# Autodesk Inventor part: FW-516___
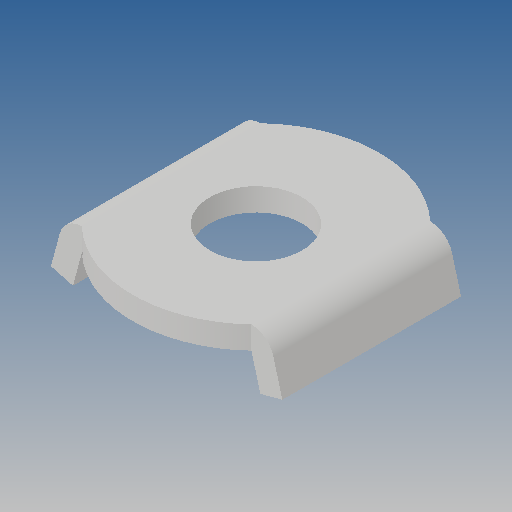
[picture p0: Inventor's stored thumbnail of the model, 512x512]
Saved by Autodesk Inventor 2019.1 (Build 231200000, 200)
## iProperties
Created: 2010-06
Part Number: FW-516___
Material: Ogólny
Document SubType Name: Modeling
Designer: CADENGINEERING4
Density: 1 g/cm^3
Appearance: Domyślna
Author: CADENGINEERING4
Revision Number: ANY
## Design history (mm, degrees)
feature "NONE"
node "Bryła1"
